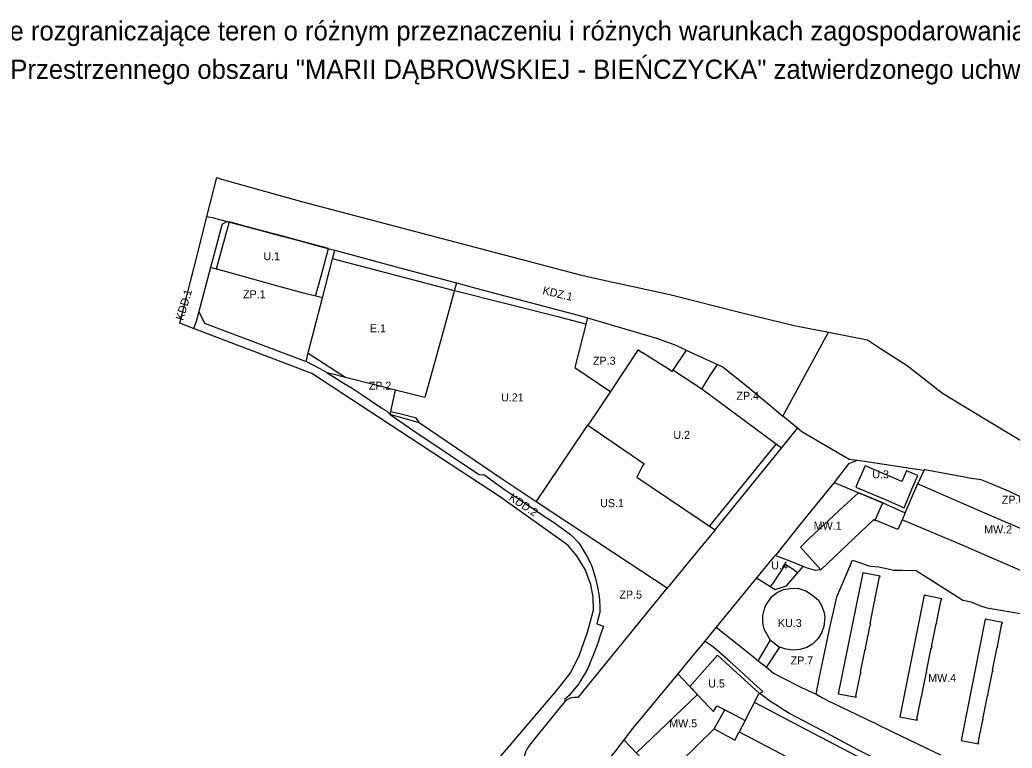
# Model space of a CAD drawing. Extents: x 7428689 to 7430424, y 5549101 to 5550539.
# Drawn here: x 7429279 to 7429899, y 5550084 to 5550539 of the extents above; entities that cross this region are included whole.
import ezdxf

# ---------------------------------------------------------------- set-up
doc = ezdxf.new("R2010")
doc.units = 0
for name, color, linetype in [('info', 7, 'Continuous'), ('linie rozgraniczające', 7, 'Continuous'), ('nieprzekraczalne linie zabudowy', 7, 'Continuous'), ('obowiazujace linie zabudowy', 7, 'Continuous'), ('przeznaczenia terenów', 7, 'Continuous')]:
    doc.layers.add(name, color=color, linetype=linetype)

msp = doc.modelspace()

# ---------------------------------------------------------------- linework, layer by layer
at = {"layer": 'linie rozgraniczające'}
for points in [[(7429395.87, 5550416.55), (7429402, 5550440.81), (7429405.02, 5550439.87), (7429454.97, 5550425.86), (7429629.82, 5550379.8), (7429641.97, 5550377.14), (7429685.13, 5550367.7), (7429731.17, 5550356.06), (7429762.72, 5550348.49), (7429784.16, 5550344.24)], [(7429387.53, 5550346.57), (7429379.01, 5550349.81), (7429390.13, 5550393.85), (7429395.87, 5550416.55)], [(7429395.87, 5550416.55), (7429400.22, 5550415.6), (7429401.48, 5550415.34), (7429408.53, 5550413.45)], [(7429408.53, 5550413.45), (7429405.35, 5550411.68), (7429404.58, 5550408.79), (7429401.03, 5550395.53), (7429400.42, 5550393.24), (7429398.1, 5550384.59)], [(7429408.53, 5550413.45), (7429428.21, 5550408.18), (7429441.31, 5550404.68), (7429449.38, 5550402.52), (7429456.15, 5550400.71), (7429462.9, 5550398.9), (7429471.44, 5550396.62), (7429474.82, 5550395.71), (7429475.78, 5550395.45)], [(7429468.07, 5550365.62), (7429474.41, 5550390.12), (7429475.78, 5550395.45)], [(7429475.78, 5550395.45), (7429516.35, 5550384.55), (7429551.87, 5550375.03)], [(7429398.1, 5550384.59), (7429390.78, 5550357.2)], [(7429468.07, 5550365.62), (7429456.26, 5550368.62), (7429440.23, 5550372.99), (7429410.34, 5550381.28), (7429398.1, 5550384.59)], [(7429551.87, 5550375.03), (7429543.45, 5550344.64), (7429533.9, 5550310.22), (7429532.03, 5550303.44), (7429513.74, 5550308.12)], [(7429551.87, 5550375.03), (7429563.98, 5550371.78), (7429620.8, 5550356.82)], [(7429457.82, 5550326.01), (7429459.42, 5550332.19), (7429468.07, 5550365.62)], [(7429390.78, 5550357.2), (7429390.16, 5550354.9), (7429389.13, 5550351.03), (7429387.53, 5550346.57)], [(7429390.78, 5550357.2), (7429394.33, 5550349.94), (7429457.82, 5550326.01)], [(7429620.8, 5550356.82), (7429627.88, 5550354.96), (7429632.25, 5550353.66), (7429633.69, 5550353.23)], [(7429633.69, 5550353.23), (7429625.83, 5550322.22), (7429647.7, 5550307.32), (7429647.94, 5550307.16)], [(7429633.69, 5550353.23), (7429676.8, 5550340.46), (7429688.77, 5550336.13)], [(7429585.15, 5550063.36), (7429573.41, 5550072.44), (7429615.16, 5550121.37), (7429623.18, 5550131.69), (7429628.73, 5550142.8), (7429633.73, 5550156.94), (7429637.36, 5550170.6), (7429637.27, 5550178.76), (7429635.82, 5550186.66), (7429632.23, 5550195.98), (7429627.06, 5550204.65), (7429621.44, 5550211.32), (7429578.76, 5550241.61), (7429461.51, 5550318.42), (7429387.53, 5550346.57)], [(7429755.81, 5550291.79), (7429784.16, 5550344.24)], [(7429784.16, 5550344.24), (7429808.65, 5550339.38), (7429816.83, 5550334.12)], [(7429667.47, 5550331.65), (7429665.17, 5550333.16), (7429665.15, 5550333.13), (7429647.94, 5550307.16)], [(7429695.27, 5550333.13), (7429686.4, 5550319.73), (7429684.99, 5550320.71), (7429685.01, 5550320.73), (7429678.59, 5550324.71), (7429667.86, 5550331.6), (7429667.83, 5550331.58), (7429667.7, 5550331.5), (7429667.47, 5550331.65)], [(7429688.77, 5550336.13), (7429693.68, 5550333.86), (7429695.27, 5550333.13)], [(7429695.27, 5550333.13), (7429714.79, 5550324.12)], [(7429816.83, 5550334.12), (7429833.34, 5550323.51), (7429855.56, 5550306.27), (7429881.93, 5550290.04), (7429926.89, 5550263.18), (7429964.68, 5550236.86), (7430011.43, 5550186.87), (7430059.81, 5550126.71), (7430101.57, 5550076.38), (7430124.52, 5550048.84), (7430239.35, 5549907.74), (7430243.53, 5549902.67), (7430275.28, 5549864.05), (7430299.52, 5549835.73), (7430341.5, 5549786.7)], [(7429471, 5550318.91), (7429466.62, 5550321.29), (7429457.82, 5550326.01)], [(7429471, 5550318.91), (7429477.11, 5550315.04), (7429481.61, 5550312.27), (7429486.7, 5550309.36), (7429492.32, 5550305.52), (7429505.15, 5550296.85), (7429508, 5550295.07), (7429510.46, 5550292.76)], [(7429513.74, 5550308.12), (7429471, 5550318.91)], [(7429754.84, 5550271.85), (7429727.59, 5550292.09), (7429705.16, 5550308.76), (7429709.9, 5550316.51), (7429714.79, 5550324.12)], [(7429714.79, 5550324.12), (7429718.12, 5550322.58), (7429734.05, 5550309.91), (7429744.9, 5550300.88), (7429755.81, 5550291.79)], [(7429510.46, 5550292.76), (7429513.74, 5550308.12)], [(7429647.94, 5550307.16), (7429647.6, 5550306.64), (7429638.79, 5550293.56), (7429633.82, 5550286.18)], [(7429510.46, 5550292.76), (7429525.11, 5550282.67), (7429564.37, 5550256.42), (7429565.89, 5550255.43), (7429567.81, 5550255.1), (7429568.92, 5550255.34), (7429581.9, 5550245.93), (7429594.84, 5550237.36), (7429607.18, 5550228.99), (7429613.02, 5550225.14), (7429623.1, 5550217.87), (7429625.87, 5550215.06), (7429628.29, 5550212.75), (7429633.22, 5550204.46), (7429635.02, 5550200.92), (7429636.55, 5550197.43), (7429638.58, 5550190.32), (7429639.85, 5550185.08), (7429640.64, 5550181.69), (7429641.23, 5550177.4), (7429641.44, 5550172.27), (7429641.28, 5550169.26), (7429640.22, 5550164.76), (7429639.5, 5550162.12), (7429643.62, 5550160.62), (7429641.45, 5550154.16), (7429640.58, 5550151.23), (7429639.59, 5550148.45), (7429638.28, 5550145.19), (7429637.24, 5550142.54), (7429635.62, 5550138.53), (7429634.66, 5550136.19), (7429633.63, 5550133.88), (7429632.24, 5550131.34), (7429630.85, 5550128.96), (7429629.19, 5550126.58), (7429628.16, 5550124.72), (7429625.66, 5550121.62), (7429622.16, 5550117.41), (7429619.27, 5550114.75), (7429620.13, 5550114.03)], [(7429601.63, 5550238.36), (7429580.3, 5550252.42), (7429528.4, 5550287.6), (7429510.46, 5550292.76)], [(7429764.91, 5550284.22), (7429755.81, 5550291.79)], [(7429601.63, 5550238.36), (7429632, 5550283.48), (7429633.8, 5550286.15), (7429633.82, 5550286.18)], [(7429633.82, 5550286.18), (7429668.91, 5550262.31)], [(7429754.84, 5550271.85), (7429764.91, 5550284.22)], [(7429801.91, 5550264.13), (7429797.14, 5550264.84), (7429770.18, 5550280.51), (7429767.53, 5550282.05), (7429764.91, 5550284.22)], [(7429713.33, 5550220.89), (7429738.37, 5550251.62), (7429754.84, 5550271.85)], [(7429801.91, 5550264.13), (7429796.74, 5550262.04), (7429787.68, 5550250.28)], [(7429843.75, 5550257.92), (7429843.58, 5550257.85), (7429806.7, 5550263.4), (7429801.91, 5550264.13)], [(7429668.91, 5550262.31), (7429668.99, 5550262.26), (7429667.77, 5550260.36), (7429664.39, 5550253.73), (7429713.1, 5550221.05), (7429713.33, 5550220.89)], [(7429843.75, 5550257.92), (7429840.08, 5550249.7)], [(7429974.55, 5550190.8), (7429972.48, 5550192.99), (7429960.54, 5550204.88), (7429951.74, 5550211.88), (7429945.88, 5550216.54), (7429927.77, 5550228.95), (7429913.66, 5550237.27), (7429901.94, 5550242.49), (7429897.67, 5550244.65), (7429884.92, 5550250.06), (7429879.58, 5550252.11), (7429872.23, 5550253.14), (7429869.16, 5550253.7), (7429844.49, 5550258.25), (7429843.75, 5550257.92)], [(7429787.68, 5550250.28), (7429766.79, 5550224.58), (7429751.53, 5550205.46), (7429750.95, 5550204.86)], [(7429787.68, 5550250.28), (7429798.16, 5550245.92), (7429818.02, 5550237.77), (7429818, 5550237.73), (7429818.1, 5550237.74), (7429832.23, 5550231.52)], [(7429832.23, 5550231.52), (7429840.08, 5550249.7)], [(7429840.08, 5550249.7), (7429841.04, 5550249.22), (7429881.63, 5550231.45), (7429907.93, 5550220.14), (7429952.95, 5550200.66), (7429974.55, 5550190.8)], [(7429683.54, 5550184.32), (7429659.72, 5550200.03), (7429601.63, 5550238.36)], [(7429830.34, 5550227.16), (7429827.66, 5550220.98), (7429812.56, 5550227.35), (7429779.48, 5550195.78), (7429776.03, 5550195.36), (7429770.27, 5550197.12), (7429768.46, 5550197.85)], [(7429832.23, 5550231.52), (7429830.34, 5550227.16)], [(7429965.52, 5550177.42), (7429964.79, 5550176.7), (7429963.7, 5550175.14), (7429960.95, 5550171.21), (7429960.63, 5550170.77), (7429960.63, 5550170.77), (7429950.64, 5550175.25), (7429868.83, 5550210.74), (7429830.34, 5550227.16)], [(7429713.33, 5550220.89), (7429697.59, 5550201.57), (7429683.54, 5550184.32)], [(7429750.95, 5550204.86), (7429749.82, 5550203.69), (7429739.22, 5550190.74)], [(7429768.46, 5550197.85), (7429761.25, 5550200.76), (7429753.61, 5550203.84), (7429750.95, 5550204.86)], [(7429776.57, 5550118.1), (7429778.44, 5550127.9), (7429785.41, 5550161.6), (7429787.27, 5550169.59), (7429789.47, 5550179.04), (7429790.65, 5550181.84), (7429795.63, 5550193.6), (7429799.16, 5550201.95), (7429804.33, 5550200.14), (7429809.34, 5550198.38), (7429810.9, 5550198.22), (7429815.79, 5550197.71), (7429821.49, 5550196.51), (7429824.76, 5550195.72), (7429830.36, 5550195.59), (7429838.93, 5550195.4), (7429847.51, 5550189.96), (7429859.02, 5550182.66), (7429865.31, 5550178.67), (7429868.24, 5550176.82), (7429873.38, 5550175.79), (7429878.66, 5550173.61), (7429883.2, 5550172.13), (7429890.65, 5550170.87), (7429905.27, 5550168.41)], [(7429739.22, 5550190.74), (7429750.92, 5550183.52), (7429758.06, 5550185.74), (7429768.46, 5550197.85)], [(7429739.22, 5550190.74), (7429714.12, 5550160.06)], [(7429620.13, 5550114.03), (7429621.04, 5550114.82), (7429622.31, 5550115.5), (7429623.74, 5550116.05), (7429625.64, 5550116.29), (7429626.91, 5550116.41), (7429628.1, 5550116.37), (7429683.54, 5550184.32)], [(7429740.39, 5550139.06), (7429747.95, 5550151.9), (7429746.87, 5550153.63), (7429744.08, 5550158.79), (7429743.18, 5550163.03), (7429743.2, 5550167.38), (7429743.96, 5550170.64), (7429744.97, 5550173.31), (7429748.91, 5550179.09), (7429752.26, 5550181.7), (7429756.23, 5550183.51), (7429760.5, 5550184.25), (7429764.79, 5550184.44), (7429767.02, 5550183.86), (7429770.46, 5550182.58), (7429774.43, 5550179.9), (7429777.91, 5550176.9), (7429780.06, 5550173.22), (7429781.58, 5550169.06), (7429781.85, 5550166.12), (7429781.27, 5550160.4), (7429779.89, 5550156.3), (7429777.57, 5550152.64), (7429774.38, 5550149.68), (7429770.7, 5550147.37), (7429766.46, 5550146.06), (7429762.13, 5550145.74), (7429757.77, 5550146.27), (7429753.65, 5550147.56), (7429745.49, 5550135.23), (7429745.42, 5550135.03)], [(7429714.12, 5550160.06), (7429711.18, 5550156.49), (7429706.69, 5550151.04)], [(7429714.12, 5550160.06), (7429735.27, 5550143.15), (7429737.64, 5550141.26), (7429740.39, 5550139.06)], [(7429706.69, 5550151.04), (7429695.52, 5550137.47), (7429690.14, 5550130.95)], [(7429741.17, 5550118.66), (7429743.26, 5550119.87), (7429739.6, 5550123.05), (7429734.96, 5550127.38), (7429731.79, 5550130.31), (7429726.51, 5550135.12), (7429722.5, 5550138.65), (7429717.34, 5550143.17), (7429712.62, 5550147.3), (7429709.72, 5550149.44), (7429707.74, 5550150.71), (7429706.69, 5550151.04)], [(7429740.39, 5550139.06), (7429741.01, 5550138.6), (7429745.42, 5550135.03)], [(7429745.42, 5550135.03), (7429748.18, 5550132.8), (7429749.86, 5550131.28), (7429754.76, 5550128.76), (7429759.22, 5550126.48), (7429764.12, 5550124.04), (7429767.43, 5550122.28), (7429776.57, 5550118.1)], [(7429690.14, 5550130.95), (7429661.84, 5550096.64), (7429656.47, 5550089.67)], [(7429690.14, 5550130.95), (7429709.59, 5550110.16), (7429712.44, 5550107.31), (7429714.44, 5550110.92), (7429722.86, 5550106.71), (7429732.25, 5550101.83)], [(7429585.15, 5550063.36), (7429586.69, 5550065.24), (7429591.91, 5550071.67), (7429592.5, 5550072.73), (7429592.96, 5550073.85), (7429593.59, 5550076), (7429593.98, 5550077.82), (7429594.75, 5550080.83), (7429595.18, 5550082.22), (7429596.04, 5550083.81), (7429596.76, 5550085.13), (7429597.72, 5550086.32), (7429603.54, 5550093.53), (7429609.86, 5550101.47), (7429615.12, 5550107.92), (7429618.82, 5550112.61), (7429620.13, 5550114.03)], [(7429732.25, 5550101.83), (7429740.7, 5550118.36), (7429741.17, 5550118.66)], [(7429869.25, 5550048.21), (7429852.78, 5550056.98), (7429830.56, 5550068.73), (7429820.17, 5550074.14), (7429810.58, 5550079.43), (7429802.65, 5550083.47), (7429791.4, 5550089.42), (7429780.49, 5550095.18), (7429764.74, 5550103.58), (7429759.94, 5550106.04), (7429756.81, 5550108.06), (7429752.32, 5550110.84), (7429748.27, 5550113.3), (7429743.03, 5550117.31), (7429741.17, 5550118.66)], [(7429776.57, 5550118.1), (7429780.47, 5550115.99), (7429783.38, 5550114.41), (7429783.56, 5550114.31), (7429801.58, 5550105.71), (7429808.76, 5550102.25), (7429813.33, 5550100.03), (7429817.87, 5550097.84), (7429820.5, 5550096.56), (7429823.46, 5550095.13), (7429845.5, 5550084.48), (7429854.32, 5550080.21)], [(7429732.25, 5550101.83), (7429728.53, 5550094.56)], [(7429656.47, 5550089.67), (7429676.37, 5550068.6), (7429677.06, 5550069.42), (7429681.08, 5550065.54), (7429712.8, 5550096.5), (7429725.68, 5550089.53), (7429728.53, 5550094.56)], [(7429656.47, 5550089.67), (7429651.14, 5550082.75), (7429621.81, 5550047.22), (7429620.82, 5550046.08)], [(7429728.53, 5550094.56), (7429856.2, 5550027.54), (7429857.77, 5550026.87)]]:
    msp.add_lwpolyline(points, dxfattribs=at)
at = {"layer": 'nieprzekraczalne linie zabudowy'}
for points in [[(7429409.72, 5550413.13), (7429401.69, 5550383.62)], [(7429463.74, 5550366.72), (7429467.5, 5550380.07), (7429471.83, 5550396.51), (7429456.15, 5550400.71), (7429442.43, 5550404.38), (7429427.3, 5550408.42), (7429409.72, 5550413.13)], [(7429632.68, 5550349.25), (7429616.8, 5550353.45), (7429550.52, 5550370.15), (7429474.41, 5550390.12)], [(7429459.15, 5550331.15), (7429482.66, 5550315.97)], [(7429705.16, 5550308.76), (7429687.01, 5550320.64)], [(7429510.89, 5550294.79), (7429517.87, 5550293.02), (7429525.92, 5550290.99), (7429526.3, 5550290.89), (7429528.4, 5550287.6)], [(7429709.99, 5550223.13), (7429710.23, 5550223.42), (7429751.62, 5550274.23)], [(7429806.75, 5550259.88), (7429801.78, 5550248.51), (7429801.31, 5550247.49), (7429821.63, 5550238.85), (7429830.1, 5550235.19), (7429831.52, 5550234.58), (7429836.36, 5550246.14), (7429840.07, 5550254.82), (7429833.08, 5550257.76), (7429830.12, 5550250.93), (7429810.17, 5550259.55), (7429808.33, 5550260.34), (7429807.16, 5550260.78), (7429806.75, 5550259.88)], [(7429813.28, 5550226.49), (7429818.1, 5550237.74), (7429810.22, 5550240.97), (7429802.95, 5550243.96), (7429793.89, 5550235.68), (7429772.21, 5550215.31), (7429766.67, 5550210.02), (7429779.48, 5550195.78)], [(7429764.99, 5550193.82), (7429762.69, 5550195.59), (7429761.55, 5550196.54), (7429757.23, 5550199.24), (7429749.19, 5550187.09), (7429747.8, 5550185.44)], [(7429747.95, 5550151.9), (7429753.65, 5550147.56)], [(7429897.08, 5550029.43), (7429856.35, 5550050.99), (7429811.15, 5550074.65), (7429774.92, 5550093.62), (7429753.78, 5550104.68), (7429737.98, 5550113.04), (7429740.7, 5550118.36), (7429741.17, 5550118.66), (7429714.95, 5550142.63), (7429697.59, 5550122.98), (7429702.3, 5550117.95), (7429664.22, 5550081.46)], [(7429712.8, 5550096.5), (7429719.48, 5550108.4)]]:
    msp.add_lwpolyline(points, dxfattribs=at)
at = {"layer": 'obowiazujace linie zabudowy'}
for points in [[(7429805.6, 5550193.98), (7429790.38, 5550118.31), (7429801.47, 5550116.21), (7429801.62, 5550116.92), (7429801.31, 5550116.98), (7429804.14, 5550131.12), (7429804.44, 5550131.06), (7429804.59, 5550131.77), (7429804.28, 5550131.83), (7429807.17, 5550146.28), (7429807.48, 5550146.22), (7429807.62, 5550146.92), (7429807.31, 5550146.99), (7429810.18, 5550161.36), (7429810.49, 5550161.3), (7429810.63, 5550162), (7429810.32, 5550162.06), (7429813.05, 5550176.29), (7429813.27, 5550176.24), (7429813.43, 5550176.96), (7429813.17, 5550177.04), (7429816.02, 5550191.36), (7429816.3, 5550191.31), (7429816.42, 5550191.83), (7429805.6, 5550193.98)], [(7429828.72, 5550104.02), (7429839.64, 5550101.88), (7429839.77, 5550102.49), (7429839.42, 5550102.56), (7429842.32, 5550116.93), (7429842.65, 5550116.86), (7429842.79, 5550117.55), (7429842.5, 5550117.61), (7429845.37, 5550131.83), (7429845.65, 5550131.78), (7429845.77, 5550132.38), (7429845.46, 5550132.44), (7429848.41, 5550147.02), (7429848.78, 5550146.95), (7429848.92, 5550147.66), (7429848.68, 5550147.71), (7429851.6, 5550162.16), (7429851.81, 5550162.12), (7429851.94, 5550162.74), (7429851.65, 5550162.8), (7429854.56, 5550177.18), (7429854.83, 5550177.13), (7429854.97, 5550177.78), (7429844.07, 5550179.98), (7429828.72, 5550104.02)], [(7429867.14, 5550089.25), (7429877.97, 5550087.08), (7429878.09, 5550087.71), (7429877.84, 5550087.76), (7429880.67, 5550102.05), (7429880.88, 5550102.01), (7429880.98, 5550102.53), (7429880.76, 5550102.57), (7429883.65, 5550117.13), (7429883.88, 5550117.09), (7429884, 5550117.68), (7429883.74, 5550117.73), (7429886.63, 5550132.31), (7429886.99, 5550132.24), (7429887.16, 5550133.05), (7429886.74, 5550133.14), (7429889.58, 5550147.46), (7429889.91, 5550147.4), (7429890.02, 5550147.93), (7429889.75, 5550147.99), (7429892.59, 5550162.32), (7429892.86, 5550162.26), (7429892.99, 5550162.94), (7429882.19, 5550165.08), (7429867.14, 5550089.25)]]:
    msp.add_lwpolyline(points, dxfattribs=at)

# ---------------------------------------------------------------- texts
at = {"layer": 'info'}
for s, p in [('Materiał pomocniczy zawierający linie rozgraniczające teren o różnym przeznaczeniu i różnych warunkach zagospodarowania terenu, ', (7429013.9, 5550526.49)), ('opracowane w skali 1:1000 pochodzące z Miejscowego Planu Zagospodarowania Przestrzennego obszaru "MARII DĄBROWSKIEJ - BIEŃCZYCKA" zatwierdzonego uchwałą RMK Nr LXI/1324/16 z dnia 21 grudnia 2016 r.', (7428687.86, 5550502.49))]:
    msp.add_text(s, height=12, dxfattribs=at).set_placement(p)
at = {"layer": 'przeznaczenia terenów'}
for s, p in [('U.1', (7429431.18, 5550389.23)), ('ZP.1', (7429418.47, 5550365.46)), ('E.1', (7429497.74, 5550344.2)), ('ZP.3', (7429637.08, 5550323.94)), ('ZP.2', (7429497.01, 5550308.34)), ('ZP.4', (7429726.72, 5550302.05)), ('U.21', (7429579.67, 5550301.05)), ('U.2', (7429687.3, 5550277.64)), ('U.3', (7429811.61, 5550252.97)), ('US.1', (7429641.58, 5550234.99)), ('ZP.6', (7429892.51, 5550237.11)), ('MW.1', (7429774.99, 5550220.87)), ('MW.2', (7429881.49, 5550218.56)), ('U.4', (7429748.43, 5550196.12)), ('ZP.5', (7429653.61, 5550177.89)), ('KU.3', (7429752.65, 5550160.11)), ('ZP.7', (7429760.55, 5550136.73)), ('U.5', (7429709.11, 5550122.35)), ('MW.4', (7429846.54, 5550125.82)), ('MW.5', (7429684.7, 5550097.44))]:
    msp.add_text(s, height=5, dxfattribs=at).set_placement(p)
for s, rotation, p in [('KDD.1', 73.2157, (7429380.99, 5550351.25)), ('KDZ.1', 346.67303, (7429605.29, 5550368.13)), ('KDD.2', 326.06265, (7429584.19, 5550239.83))]:
    msp.add_text(s, height=5, rotation=rotation, dxfattribs=at).set_placement(p)

doc.saveas('drawing.dxf')
